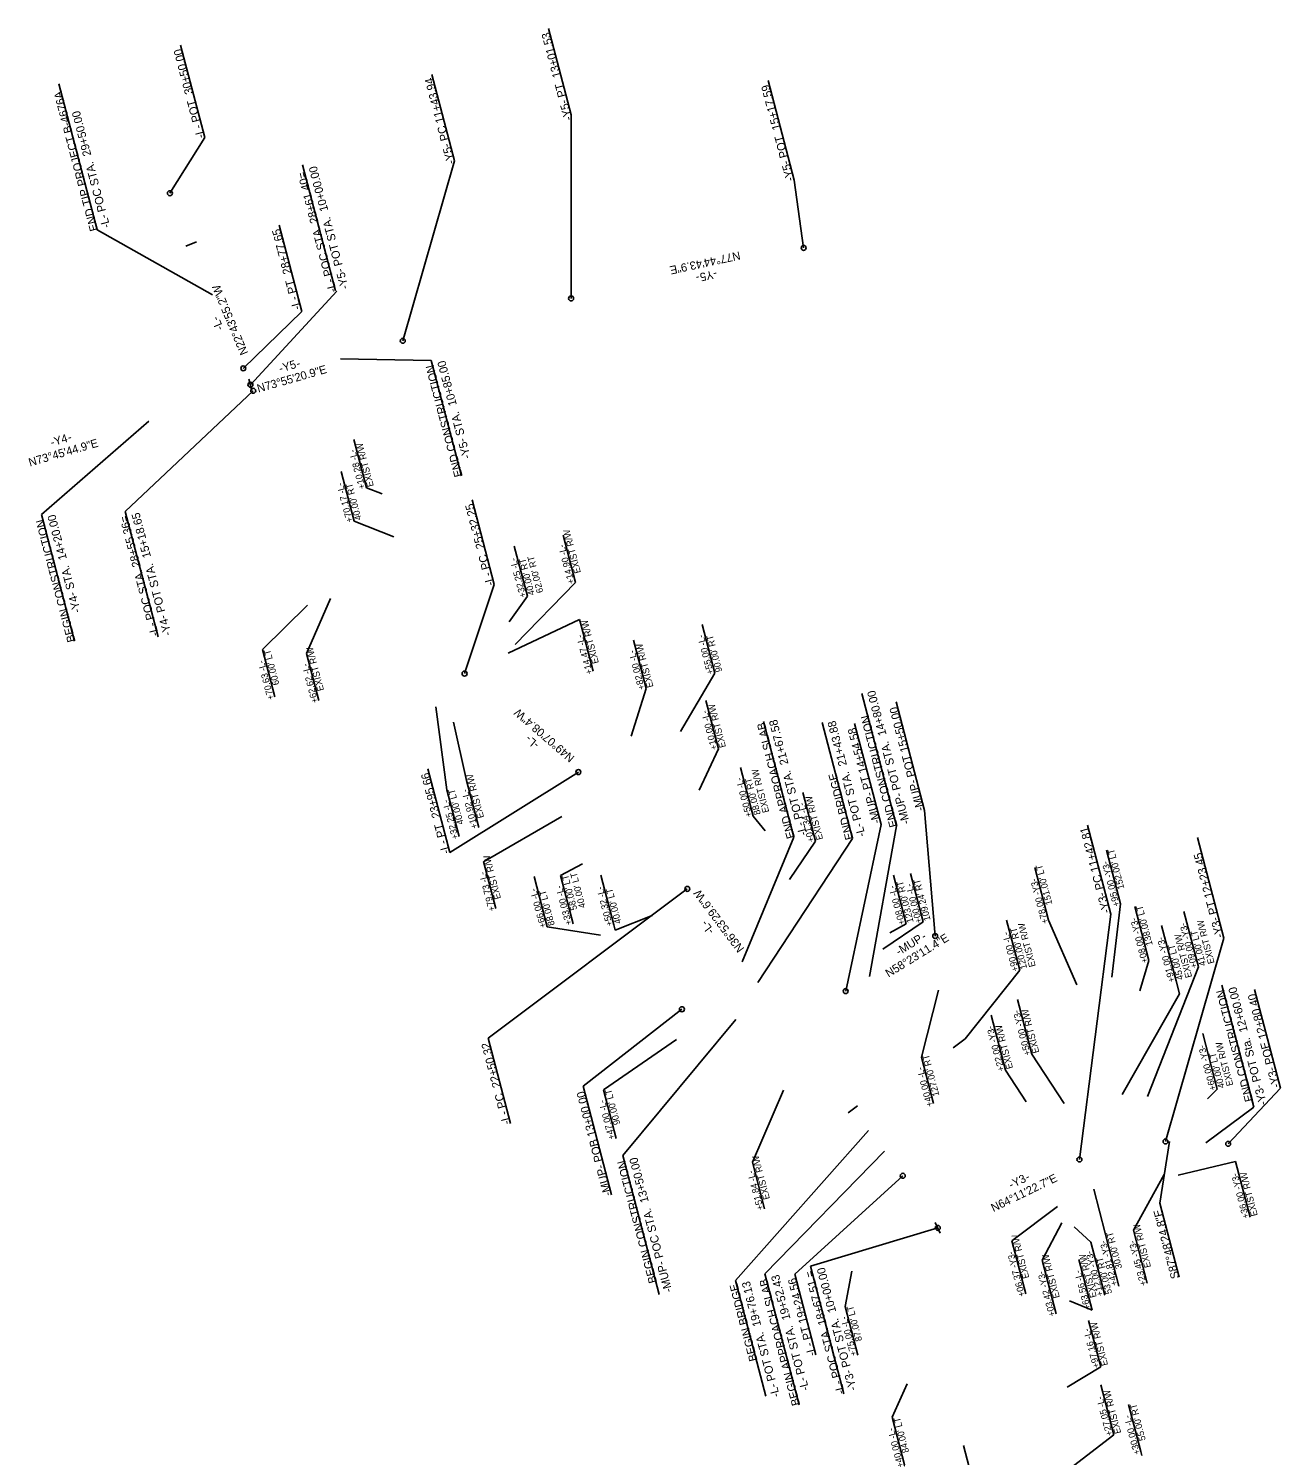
# Model space of a CAD drawing. Extents: x 1366624 to 1367908, y 878728 to 880804.
# Drawn here: x 1366624 to 1367760, y 879509 to 880804 of the extents above; entities that cross this region are included whole.
import ezdxf

# ---------------------------------------------------------------- set-up
doc = ezdxf.new("R2010")
doc.units = 0
for name, color, linetype in [('HNTB LOGO CELL', 7, 'Continuous'), ('HNTB Spark', 7, 'Continuous'), ('Old_Level_23', 7, 'Continuous'), ('Sheet Clip Boundary CELL', 7, 'Continuous'), ('Sheet Plan And Profile CELL', 7, 'Continuous'), ('Sheet Plot Border Inside CELL', 7, 'Continuous'), ('Sheet Plot Border Outside CELL', 7, 'Continuous'), ('Sheet Sticker Exception Certification CELL', 7, 'Continuous'), ('Sheet Sticker Incomplete CELL', 7, 'Continuous'), ('V7_40', 7, 'Continuous')]:
    doc.layers.add(name, color=color, linetype=linetype)

msp = doc.modelspace()

# ---------------------------------------------------------------- linework, layer by layer
at = {"layer": 'HNTB LOGO CELL'}
for p, q in [((1366766.6, 880606.7), (1366776.4, 880610.8)), ((1366823.8, 880486.2), (1366826.7, 880475.9)), ((1367367.9, 879819.8), (1367376.4, 879826.2)), ((1367447, 879720.2), (1367451.6, 879710.6))]:
    msp.add_line(p, q, dxfattribs=at)
at = {"layer": 'HNTB Spark'}
for p, q in [((1367326.9, 880110.7), (1367338.4, 880066.7)), ((1367686.1, 879952.4), (1367672.8, 880002.8)), ((1367523.7, 879949.4), (1367511.8, 879994.7)), ((1367665.7, 879939.6), (1367652.5, 879990.1)), ((1367449.8, 879931.3), (1367434.4, 879870.5)), ((1367434.4, 879870.5), (1367445.5, 879828.2)), ((1367544, 879686.2), (1367562, 879719.9)), ((1367556.8, 879637.4), (1367544, 879686.2))]:
    msp.add_line(p, q, dxfattribs=at)
for points in [[(1367338.4, 880066.7), (1367314.7, 880031.6)], [(1367523.7, 879949.4), (1367474.1, 879887)], [(1367686.1, 879952.4), (1367639.6, 879834.8)], [(1367665.7, 879939.6), (1367668.8, 879927.8), (1367616.6, 879836.4)]]:
    msp.add_lwpolyline(points, dxfattribs=at)
at = {"layer": 'Old_Level_23'}
for p, q in [((1367116.4, 880726.1), (1367095.9, 880804.5)), ((1366784, 880705.4), (1366761.9, 880789.5)), ((1366651.3, 880754.3), (1366686, 880621.8)), ((1367010.5, 880684.2), (1366990, 880762.6)), ((1367319, 880666.7), (1367295.3, 880757.3)), ((1367116.4, 880559.4), (1367116.4, 880726.1)), ((1366752.2, 880654.9), (1366784, 880705.4)), ((1366902.5, 880566.2), (1366872.5, 880680.6)), ((1366963.6, 880520.9), (1367010.5, 880684.2)), ((1367327.5, 880605.3), (1367319, 880666.7)), ((1366790.9, 880562.7), (1366686, 880621.8)), ((1366871.8, 880547.5), (1366851.3, 880625.9)), ((1366825.3, 880481), (1366903.6, 880566)), ((1366818.8, 880495.9), (1366871.8, 880547.5)), ((1366907, 880504.6), (1366989.5, 880503.1)), ((1367017, 880398.2), (1366989.5, 880503.1)), ((1366827.8, 880475.5), (1366711.6, 880366)), ((1366733, 880447.9), (1366635.5, 880363.3)), ((1367046.7, 880299.5), (1367026.5, 880376.6)), ((1366665.7, 880248.1), (1366635.5, 880363.3)), ((1366741.5, 880252), (1366711.6, 880366)), ((1367019.7, 880218.7), (1367046.7, 880299.5)), ((1367411.9, 880080.4), (1367380.4, 880200.7)), ((1367437.2, 880094.3), (1367411.4, 880193.1)), ((1367291.1, 880175.3), (1367318.6, 880070.1)), ((1367344.2, 880174.2), (1367371.8, 880069)), ((1367397.8, 880081.7), (1367373.7, 880173.4)), ((1367006.3, 880056.4), (1366986.4, 880132.3)), ((1367123, 880129.3), (1367006.3, 880056.4)), ((1367446.9, 879980.4), (1367437.2, 880094.3)), ((1367365.7, 879930.4), (1367397.8, 880081.7)), ((1367387.3, 879943.7), (1367411.9, 880080.4)), ((1367606.4, 880000.2), (1367585.2, 880081.1)), ((1367271.6, 879957.1), (1367318.6, 880070.1)), ((1367285.8, 879938.1), (1367371.8, 880069)), ((1367709.1, 879978.6), (1367685.2, 880069.8)), ((1367221.9, 880023.2), (1367041.2, 879887.6)), ((1367577.9, 879777.5), (1367606.4, 880000.2)), ((1367656, 879793.9), (1367709.1, 879978.6)), ((1367707.2, 879935.8), (1367736.3, 879824.9)), ((1367760.4, 879842.4), (1367736.9, 879931.9)), ((1367217, 879913.9), (1367127.3, 879844.2)), ((1367265.9, 879904.6), (1367163.3, 879781.1)), ((1367061.4, 879810.3), (1367041.2, 879887.6)), ((1367153.2, 879745.4), (1367127.3, 879844.2)), ((1367712.9, 879791.7), (1367760.4, 879842.4)), ((1367692.5, 879792.5), (1367736.3, 879824.9)), ((1367386.5, 879803.9), (1367265.7, 879667.7)), ((1367196.4, 879655), (1367163.3, 879781.1)), ((1367400.8, 879785), (1367292.3, 879673.6)), ((1367417.5, 879762.7), (1367319.5, 879673.3)), ((1367449.3, 879715.4), (1367333.7, 879680.5)), ((1367358.6, 879585.4), (1367333.7, 879680.5)), ((1367358.6, 879585.4), (1367333.7, 879680.5)), ((1367364.1, 879564.7), (1367333.7, 879680.5)), ((1367293.3, 879562.5), (1367265.7, 879667.7)), ((1367323.5, 879554.7), (1367292.3, 879673.6)), ((1367338.7, 879600.1), (1367319.5, 879673.3))]:
    msp.add_line(p, q, dxfattribs=at)
msp.add_lwpolyline([(1367659.7, 879793.7), (1367650.9, 879737.7), (1367668.5, 879670.6)], dxfattribs=at)
for centre in [(1366752.2, 880654.9), (1367327.5, 880605.3), (1367116.4, 880559.4), (1366963.6, 880520.9), (1366818.8, 880495.9), (1366825.3, 880481), (1366827.8, 880475.5), (1367019.7, 880218.7), (1367123, 880129.3), (1367221.9, 880023.2), (1367446.9, 879980.4), (1367365.7, 879930.4), (1367217, 879913.9), (1367656, 879793.9), (1367712.9, 879791.7), (1367577.9, 879777.5), (1367417.5, 879762.7), (1367449.3, 879715.4)]:
    msp.add_circle(centre, 2.25, dxfattribs=at)
at = {"layer": 'Sheet Clip Boundary CELL'}
for p, q in [((1367094.8, 879988.9), (1367082.9, 880034.4)), ((1367106.7, 880035.5), (1367118.2, 879991.5)), ((1367145.7, 879840.7), (1367157.2, 879796.7)), ((1367365.3, 879643.9), (1367376.8, 879599.9)), ((1367407.8, 879543.4), (1367421.6, 879573.9)), ((1367419.4, 879499.1), (1367407.8, 879543.4))]:
    msp.add_line(p, q, dxfattribs=at)
for points in [[(1367106.7, 880035.5), (1367126.6, 880046)], [(1367094.8, 879988.9), (1367143.2, 879981.2)], [(1367145.7, 879840.7), (1367212, 879886.6)], [(1367365.3, 879643.9), (1367371.4, 879676)]]:
    msp.add_lwpolyline(points, dxfattribs=at)
at = {"layer": 'Sheet Plot Border Inside CELL'}
for p, q in [((1366907.5, 880402.3), (1366919.4, 880357.1)), ((1367124.1, 880267.9), (1367059.3, 880237.3)), ((1367125.5, 880262.5), (1367124.1, 880267.9)), ((1367125.5, 880262.5), (1367136.5, 880220.8)), ((1366876.2, 880237), (1366887.4, 880194.4)), ((1367021.5, 880121.5), (1367032.6, 880078.9)), ((1367003.6, 880113.3), (1367014.8, 880070.7)), ((1367037, 880047.9), (1367108, 880089.1)), ((1367036.9, 880048), (1367048.1, 880005.4)), ((1367143.4, 880035.6), (1367155.3, 879990.5)), ((1367156.5, 879985.8), (1367189.9, 879999.2)), ((1367155.3, 879990.5), (1367156.5, 879985.8)), ((1367281, 879775.2), (1367309.1, 879840.5)), ((1367281, 879775.2), (1367292.1, 879732.6)), ((1367627, 879713.3), (1367654.9, 879763.9)), ((1367601.2, 879710.6), (1367590.9, 879750.5)), ((1367626.9, 879713.4), (1367639.5, 879665.3)), ((1367516.5, 879703.5), (1367529.1, 879655.4)), ((1367601.2, 879710.6), (1367613.8, 879662.5)), ((1367597.2, 879572.8), (1367609.1, 879527.5)), ((1367472.6, 879517.9), (1367484.6, 879472))]:
    msp.add_line(p, q, dxfattribs=at)
for points in [[(1366919.4, 880357.1), (1366955.6, 880343)], [(1366876.2, 880237), (1366898, 880286.9)], [(1367003.6, 880113.3), (1366993.5, 880188.5)], [(1367021.5, 880121.5), (1367009.7, 880174.5)], [(1367516.5, 879703.5), (1367558.1, 879734.7)], [(1367609.1, 879527.5), (1367564.5, 879493.2)]]:
    msp.add_lwpolyline(points, dxfattribs=at)
at = {"layer": 'Sheet Plot Border Outside CELL'}
for p, q in [((1367615.2, 880009.6), (1367602.4, 880058.3)), ((1367549.9, 879994.9), (1367537.4, 880042.7)), ((1367641, 879958.2), (1367628.1, 880007.1)), ((1367521.7, 879922.8), (1367534.8, 879873)), ((1367497.8, 879908.5), (1367510.9, 879858.7))]:
    msp.add_line(p, q, dxfattribs=at)
for points in [[(1367615.2, 880009.6), (1367607.3, 879943.2)], [(1367549.9, 879994.9), (1367575.5, 879936.2)], [(1367641, 879958.2), (1367632.8, 879930.5)], [(1367534.8, 879873), (1367563.9, 879828.2)], [(1367510.9, 879858.7), (1367529.4, 879829.9)]]:
    msp.add_lwpolyline(points, dxfattribs=at)
at = {"layer": 'Sheet Sticker Exception Certification CELL'}
msp.add_line((1367463.3, 879878.9), (1367474.2, 879887.1), dxfattribs=at)
at = {"layer": 'Sheet Sticker Incomplete CELL'}
for p, q in [((1366919, 880431.4), (1366930.5, 880387.4)), ((1367120.4, 880301.5), (1367109.1, 880344.4)), ((1367076.7, 880289), (1367064.8, 880334.4)), ((1367076.7, 880289), (1367060.3, 880265.6)), ((1367235.4, 880263.2), (1367246.9, 880219.1)), ((1367172.9, 880249.1), (1367184.4, 880205.1)), ((1366847.4, 880197.5), (1366836.1, 880240.5)), ((1367246.9, 880219.1), (1367215.8, 880166.2)), ((1367184.4, 880205.1), (1367170.8, 880162)), ((1367238.7, 880194.4), (1367250.3, 880150.4)), ((1367250.3, 880150.4), (1367232.8, 880113)), ((1367270.3, 880133.4), (1367281.8, 880089.4)), ((1367424.5, 880037.2), (1367436, 879993.2)), ((1367409.1, 880035.6), (1367420.6, 879991.5)), ((1367703, 879841.4), (1367689.8, 879891.9)), ((1367719.7, 879775.7), (1367733, 879725)), ((1367588.2, 879702.5), (1367600.8, 879654.3)), ((1367589.5, 879640.7), (1367577.4, 879686.7)), ((1367586.1, 879631.4), (1367597.2, 879589.1)), ((1367633.7, 879512.2), (1367622.4, 879555.1)), ((1367633.7, 879512.2), (1367634.6, 879508.7))]:
    msp.add_line(p, q, dxfattribs=at)
for points in [[(1366930.5, 880387.4), (1366944.9, 880382)], [(1367120.4, 880301.5), (1367065.5, 880245.1)], [(1366836.1, 880240.5), (1366877.1, 880281)], [(1367281.8, 880089.4), (1367292.5, 880075.8)], [(1367436, 879993.2), (1367399.5, 879968.6)], [(1367420.6, 879991.5), (1367405.7, 879983.2)], [(1367703, 879841.4), (1367694.1, 879832.5)], [(1367719.7, 879775.7), (1367667.4, 879763.4)], [(1367588.2, 879702.5), (1367573.2, 879716.4)], [(1367589.5, 879640.7), (1367568.8, 879649.1)], [(1367597.2, 879589.1), (1367566.6, 879570.7)]]:
    msp.add_lwpolyline(points, dxfattribs=at)
at = {"layer": 'V7_40'}
for p, q in [((1367707.2, 879935.8), (1367735.6, 879827.6)), ((1367386.5, 879803.9), (1367265.7, 879667.7)), ((1367293.3, 879562.5), (1367265.7, 879667.7))]:
    msp.add_line(p, q, dxfattribs=at)

# ---------------------------------------------------------------- texts
at = {"layer": 'HNTB Spark'}
for s, p in [('EXIST R/W', (1367345.2, 880068.5)), ('+01.34 -L-', (1367337.4, 880066.5)), ("120.00' RT", (1367530.5, 879951.1)), ('EXIST R/W', (1367538.2, 879953.1)), ('+09.00 -Y3-', (1367685.1, 879952)), ('EXIST R/W', (1367700.6, 879956)), ('+90.00 -L-', (1367522.7, 879949)), ('+91.00 -Y3-', (1367664.7, 879939.2)), ('EXIST R/W', (1367680.2, 879943.3)), ("41.00' LT", (1367692.9, 879954)), ("45.00' LT", (1367672.5, 879941.3)), ("127.00' RT", (1367450.8, 879835.7)), ('+40.00 -L-', (1367445, 879826.2)), ('EXIST R/W', (1367560.1, 879652.3)), ('+03.42 -Y3-', (1367556.1, 879635.8))]:
    msp.add_text(s, height=6, rotation=104.6851, dxfattribs=at).set_placement(p)
at = {"layer": 'Old_Level_23'}
for s, p in [('-Y5- PT  13+01.53', (1367117.5, 880722)), ('-L- POT  30+50.00', (1366783.8, 880705.9)), ('-Y5- PC 11+43.94', (1367011, 880682.4)), ('-Y5- POT  15+17.59', (1367318.9, 880666.9)), ('END TIP PROJECT B-4676A', (1366687.1, 880621.5)), ('-L- POC STA.  29+50.00', (1366698, 880624.4)), ('-L- POC STA. 28+61.40=', (1366903.6, 880566)), ('-Y5- POT STA.  10+00.00', (1366914.5, 880568.8)), ('-L- PT  28+77.65', (1366871.1, 880550.1)), ('END CONSTRUCTION', (1367018, 880398.3)), ('-Y5- STA.  10+85.00', (1367025.3, 880414.8)), ('-Y4- STA.  14+20.00', (1366671.3, 880275)), ('-L- POC STA. 28+55.36=', (1366742.1, 880253.8)), ('-Y4- POT STA.  15+18.65', (1366753.6, 880254.2)), ('-L- PC  25+32.25', (1367046.7, 880299.5)), ('BEGIN CONSTRUCTION', (1366666.6, 880248.3)), ('-MUP- POT STA.  14+80.00', (1367423.9, 880083)), ('END CONSTRUCTION', (1367413, 880080.2)), ('-MUP- POT 15+50.00', (1367437.1, 880095)), ('END APPROACH SLAB', (1367319.7, 880069.9)), ('-L- POT STA.  21+67.58', (1367330.6, 880072.7)), ('-L- POT STA.  21+43.88', (1367383.7, 880071.6)), ('-MUP- PT 14+54.58', (1367397.3, 880083.6)), ('-L- PT  23+95.66', (1367006.3, 880056.2)), ('END BRIDGE', (1367372.9, 880068.8)), ('-Y3- PC 11+42.81', (1367605.8, 880002.3)), ('-Y3- PT 12+23.45', (1367708.8, 879979.8)), ('-Y3- POT Sta.  12+60.00', (1367748.2, 879827.8)), ('END CONSTRUCTION', (1367735.7, 879831)), ('-Y3- POE 12+80.40', (1367760, 879843.7)), ('-L- PC  22+50.32', (1367061.4, 879810.3)), ('-MUP- POB 13+00.00', (1367153.2, 879745.4)), ('-MUP- POC STA.  13+50.00', (1367208.3, 879657.9)), ('BEGIN CONSTRUCTION', (1367194.5, 879666.2)), ('S87°48\'24.8"E', (1367668.6, 879670.2)), ('-L- POC STA. 18+67.51 =', (1367364.9, 879565.5)), ('-Y3- POT STA.  10+00.00', (1367375.7, 879568.7)), ('BEGIN BRIDGE', (1367285.7, 879595.3)), ('-L- POT STA.  19+76.13', (1367305.9, 879562.7)), ('BEGIN APPROACH SLAB', (1367324.4, 879555)), ('-L- POT STA.  19+52.43', (1367332.5, 879568.6)), ('-L- PT 19+24.56', (1367338.7, 879600.1))]:
    msp.add_text(s, height=7.5, rotation=104.6851, dxfattribs=at).set_placement(p)
at = {"layer": 'Sheet Clip Boundary CELL'}
for s, p in [("40.00' LT", (1367129.7, 880006.6)), ('+33.00 -L-', (1367117.2, 879991.2)), ("58.00' LT", (1367122, 880004.6)), ('+66.00 -L-', (1367093.9, 879988.6)), ("88.00' LT", (1367101.6, 879990.6)), ('+47.00 -L-', (1367156.3, 879796.4)), ("90.00' LT", (1367161.1, 879809.8)), ("87.00' LT", (1367380.7, 879613.2)), ('+75.00 -L-', (1367375.9, 879599.9)), ('+40.00 -L-', (1367418.5, 879498.6)), ("84.00' LT", (1367423.3, 879511.9))]:
    msp.add_text(s, height=6, rotation=104.6851, dxfattribs=at).set_placement(p)
at = {"layer": 'Sheet Plan And Profile CELL'}
for s, rotation, p in [('N77°44\'43.9"E', 192.2545, (1367269.1, 880602.2)), ('Y5', 192.2545, (1367244.7, 880584.7)), ('-', 192.2545, (1367248.1, 880585.4)), ('N22°43\'55.2"W', 112.732, (1366823.4, 880509.9)), ('-', 192.2545, (1367232.2, 880581.9)), ('-', 112.732, (1366797.4, 880540.8)), ('L', 112.732, (1366799.7, 880535.4)), ('-', 112.732, (1366801, 880532.2)), ('N73°55\'20.9"E', 16.0775, (1366832.5, 880473.8)), ('-', 16.0775, (1366852.3, 880492)), ('Y5', 16.0775, (1366855.7, 880493)), ('-', 16.0775, (1366868, 880496.5)), ('N73°45\'44.9"E', 16.2375, (1366625.1, 880406.7)), ('-', 16.2375, (1366644.9, 880424.9)), ('Y4', 16.2375, (1366648.2, 880425.9)), ('-', 16.2375, (1366660.5, 880429.5)), ('N49°07\'08.4"W', 139.119, (1367120.1, 880143.1)), ('-', 139.119, (1367081, 880161.2)), ('L', 139.119, (1367085.4, 880157.4)), ('-', 139.119, (1367088, 880155.1)), ('N36°53\'29.6"W', 126.8915, (1367273.9, 879969)), ('-', 126.8915, (1367241.1, 879992.7)), ('L', 126.8915, (1367244.6, 879988)), ('-', 126.8915, (1367246.7, 879985.2)), ('N58°23\'11.4"E', 31.6135, (1367404.6, 879942.6)), ('MUP', 31.6135, (1367417, 879964.3)), ('-', 31.6135, (1367436.8, 879976.5)), ('-', 31.6135, (1367414, 879962.5)), ('N64°11\'22.7"E', 25.8104, (1367499.8, 879729.7)), ('-', 25.8104, (1367515.9, 879750.8)), ('Y3', 25.8104, (1367519.1, 879752.3)), ('-', 25.8104, (1367530.6, 879757.9))]:
    msp.add_text(s, height=7.5, rotation=rotation, dxfattribs=at).set_placement(p)
at = {"layer": 'Sheet Plot Border Inside CELL'}
for s, p in [('+70.17 -L-', (1366918.4, 880356.8)), ("40.00' RT", (1366926.2, 880358.8)), ('EXIST R/W', (1367141.6, 880228.5)), ('+14.47 -L-', (1367136, 880218.9)), ('EXIST R/W', (1366892.1, 880203.7)), ('+62.62 -L-', (1366886.8, 880192.8)), ('EXIST R/W', (1367037.4, 880088.2)), ('+32.25 -L-', (1367014.3, 880069.1)), ("40.00' LT", (1367018.9, 880082.4)), ('+10.92 -L-', (1367031.7, 880078.7)), ('EXIST R/W', (1367052.8, 880014.6)), ('+79.73 -L-', (1367047.6, 880003.7)), ('+50.32 -L-', (1367154.3, 879990.2)), ("40.00' LT", (1367162.1, 879992.3)), ('EXIST R/W', (1367296.9, 879741.9)), ('+51.84 -L-', (1367291.2, 879732.4)), ('EXIST R/W', (1367642.9, 879680)), ('EXIST R/W', (1367532.4, 879670.2)), ('+42.81 -Y3-', (1367612.6, 879663.6)), ("30.00' RT", (1367616.7, 879679)), ('+23.45 -Y3-', (1367639, 879663.6)), ('+06.37 -Y3-', (1367528.6, 879653.7)), ('+27.05 -L-', (1367608.1, 879527.3)), ('EXIST R/W', (1367615.8, 879529.3))]:
    msp.add_text(s, height=6, rotation=104.6851, dxfattribs=at).set_placement(p)
at = {"layer": 'Sheet Plot Border Outside CELL'}
for s, p in [("152.00' LT", (1367618.7, 880023.7)), ("151.00' LT", (1367553.4, 880009.4)), ('+95.00 -Y3-', (1367614.5, 880008)), ('+78.00 -Y3-', (1367549.6, 879992.3)), ("138.00' LT", (1367644.5, 879972.4)), ('+08.00 -Y3-', (1367640.3, 879956.7)), ('+50.00 -Y3-', (1367533.8, 879872.8)), ('EXIST R/W', (1367541.5, 879874.8)), ('+22.00 -Y3-', (1367509.9, 879858.4)), ('EXIST R/W', (1367517.6, 879860.5))]:
    msp.add_text(s, height=6, rotation=104.6851, dxfattribs=at).set_placement(p)
at = {"layer": 'Sheet Sticker Incomplete CELL'}
for s, p in [('EXIST R/W', (1366937.3, 880389.1)), ('+10.28 -L-', (1366929.6, 880387.1)), ('EXIST R/W', (1367125.3, 880310.5)), ('+14.90 -L-', (1367119.5, 880300.9)), ('+32.25 -L-', (1367075.7, 880288.6)), ("40.00' RT", (1367083.5, 880290.6)), ("62.00' RT", (1367091.2, 880292.7)), ('EXIST R/W', (1367191.2, 880206.8)), ('+55.00 -L-', (1367245.9, 880218.9)), ("90.00' RT", (1367253.7, 880220.9)), ("60.00' LT", (1366851.6, 880209)), ('+82.00 -L-', (1367183.4, 880204.8)), ('+70.63 -L-', (1366846.8, 880195.6)), ('+10.00 -L-', (1367249.3, 880150.2)), ('EXIST R/W', (1367257, 880152.2)), ('EXIST R/W', (1367296.3, 880093.2)), ('+50.00 -L-', (1367280.8, 880089.2)), ("88.00' RT", (1367288.6, 880091.2)), ('+08.00 -L-', (1367419.6, 879991.3)), ("123.00' RT", (1367427.4, 879993.3)), ('+00.00 -L-', (1367435.1, 879992.9)), ("109.24' RT", (1367442.8, 879995)), ('EXIST R/W', (1367717.6, 879845.1)), ('+60.00 -Y3-', (1367702.1, 879841)), ("40.00' LT", (1367709.8, 879843)), ('+36.00 -Y3-', (1367732, 879724.7)), ('EXIST R/W', (1367739.8, 879726.8)), ('EXIST R/W', (1367593.6, 879652.8)), ('+12.00 -Y3-', (1367599.8, 879654.1)), ("53.00' RT", (1367607.6, 879656.1)), ('+63.56 -L-', (1367588.1, 879641.9)), ('+97.16 -L-', (1367596.2, 879589)), ('EXIST R/W', (1367603.9, 879591)), ('+30.00 -L-', (1367633.1, 879510.3)), ("55.00' RT", (1367638.1, 879522.9))]:
    msp.add_text(s, height=6, rotation=104.6851, dxfattribs=at).set_placement(p)

doc.saveas('drawing.dxf')
